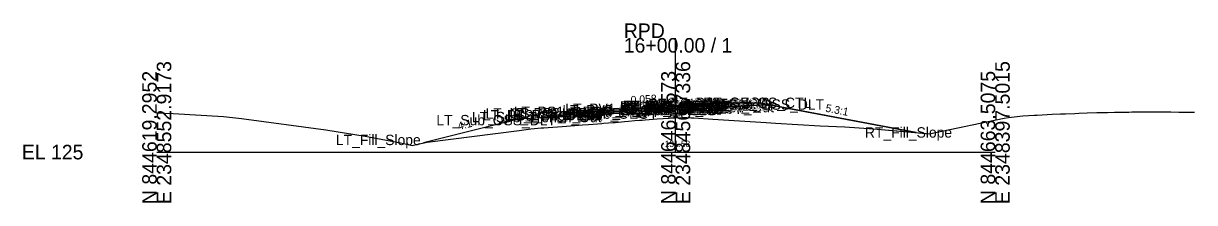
# Model space of a CAD drawing. Extents: x -26 to 2348536, y -510 to 844755.
# Drawn here: x -25.7 to 200, y 990.3 to 1024.7 of the extents above; entities that cross this region are included whole.
import ezdxf

# ---------------------------------------------------------------- set-up
doc = ezdxf.new("R2010")
doc.units = 0
for name, color, linetype in [('Default', 7, 'Continuous'), ('Exist Cross Section Cell', 7, 'Continuous'), ('Exist XS Center Line Elevation Label', 7, 'Continuous'), ('Exist XS Ground Line', 7, 'Continuous'), ('Prop CMT Pvmt Course 1', 7, 'Continuous'), ('Prop CMT Pvmt Course 2', 7, 'Continuous'), ('Prop CMT Pvmt Course 3', 7, 'Continuous'), ('Prop CMT Pvmt Surface', 7, 'Continuous'), ('Prop CMT Pvmt Surface Shoulder', 7, 'Continuous'), ('Prop CMT Shld Paved Course 1', 7, 'Continuous'), ('Prop CMT Shld Paved Course 2', 7, 'Continuous'), ('Prop CMT Shld Paved Course 3', 7, 'Continuous'), ('Prop CMT Slope Grass', 7, 'Continuous'), ('Prop CMT Subgrade Earthwork', 7, 'Continuous'), ('Prop XS Earthwork Shape', 7, 'Continuous'), ('Prop XS SE Text', 7, 'Continuous'), ('Prop XS Side Slope Text', 7, 'Continuous'), ('Scratch_Level_0', 7, 'Continuous')]:
    doc.layers.add(name, color=color, linetype=linetype)

msp = doc.modelspace()

# ---------------------------------------------------------------- linework, layer by layer
at = {"layer": 'Exist Cross Section Cell'}
for p, q in [((100, 1000), (100, 1021.92)), ((0, 1000), (100, 1000)), ((100, 1000), (161.58, 1000))]:
    msp.add_line(p, q, dxfattribs=at)
at = {"layer": 'Exist XS Ground Line'}
msp.add_lwpolyline([(0, 1007.56), (3.17, 1007.41), (12.86, 1006.84), (16.33, 1006.47), (32.6, 1004.26), (40.16, 1003.07), (46.36, 1001.88), (48.21, 1001.49), (49.24, 1001.27), (50.29, 1001.51), (52.09, 1001.91), (69.82, 1004.17), (72.12, 1004.46), (72.79, 1004.52), (74.06, 1004.63), (74.62, 1004.67), (75.4, 1004.7), (78.12, 1004.91), (80.54, 1005.11), (82.06, 1005.22), (83.2, 1005.31), (84.12, 1005.38), (85.78, 1005.5), (86.09, 1005.53), (87.03, 1005.62), (87.95, 1005.68), (88.34, 1005.7), (90.13, 1005.86), (90.94, 1005.93), (92.1, 1006.04), (93.04, 1006.13), (93.54, 1006.14), (94.15, 1006.19), (96.45, 1006.36), (98.75, 1006.54), (99.67, 1006.57), (100, 1006.58), (101.36, 1006.64), (102.15, 1006.62), (102.95, 1006.6), (103.53, 1006.58), (107.14, 1006.35), (117.43, 1005.67), (119.26, 1005.55), (127.83, 1005.04), (132.6, 1004.83), (138.12, 1004.47), (148.95, 1003.52), (149.75, 1003.68), (163.28, 1006.5), (164.11, 1006.62), (166.88, 1006.98), (167.97, 1007.02), (169.08, 1007.08), (169.66, 1007.11), (171.6, 1007.21), (172.54, 1007.26), (174.17, 1007.34), (175.13, 1007.38), (176.91, 1007.44), (177.69, 1007.5), (179.31, 1007.54), (181.17, 1007.58), (181.9, 1007.6), (183.24, 1007.63), (184.55, 1007.66), (187.34, 1007.7), (187.88, 1007.71), (189.94, 1007.72), (192.4, 1007.73), (194.21, 1007.72), (194.98, 1007.72), (195.42, 1007.72), (196.99, 1007.7), (197.8, 1007.69), (200, 1007.65)], dxfattribs=at)
at = {"layer": 'Prop CMT Pvmt Course 1'}
for p, q in [((100, 1009.01), (88, 1008.31)), ((100, 1009.01), (104, 1009.25)), ((100, 1008.76), (100, 1009.01)), ((100, 1008.76), (100, 1009.01)), ((104, 1009), (100, 1008.76)), ((100, 1008.76), (100, 1008.89)), ((100, 1008.89), (100, 1008.89)), ((100, 1008.89), (100, 1008.76)), ((100, 1008.76), (100, 1008.89)), ((100, 1008.89), (100, 1008.89)), ((100, 1008.89), (100, 1008.76)), ((104, 1009.25), (104, 1009)), ((88, 1008.06), (100, 1008.76)), ((88, 1008.31), (88, 1008.06)), ((100, 1008.76), (100, 1008.76)), ((100, 1008.76), (100, 1008.76))]:
    msp.add_line(p, q, dxfattribs=at)
at = {"layer": 'Prop CMT Pvmt Course 2'}
for p, q in [((100, 1008.76), (104, 1009)), ((104, 1009), (104, 1008.67)), ((100, 1008.76), (88, 1008.06)), ((88, 1007.73), (100, 1008.43)), ((88, 1008.06), (88, 1007.73)), ((100, 1008.43), (100, 1008.76)), ((100, 1008.43), (100, 1008.76)), ((104, 1008.67), (100, 1008.43))]:
    msp.add_line(p, q, dxfattribs=at)
at = {"layer": 'Prop CMT Pvmt Course 3'}
for p, q in [((100, 1008.43), (88, 1007.73)), ((88, 1007.4), (100, 1008.1)), ((88, 1007.73), (88, 1007.4)), ((100, 1008.43), (104, 1008.67)), ((100, 1008.1), (100, 1008.43)), ((100, 1008.1), (100, 1008.43)), ((104, 1008.33), (100, 1008.1)), ((104, 1008.67), (104, 1008.33))]:
    msp.add_line(p, q, dxfattribs=at)
at = {"layer": 'Prop CMT Pvmt Surface'}
for q in [(88, 1008.31), (104, 1009.25)]:
    msp.add_line((100, 1009.01), q, dxfattribs=at)
at = {"layer": 'Prop CMT Pvmt Surface Shoulder'}
for p, q in [((104, 1009.25), (108, 1009.48)), ((88, 1008.31), (78, 1007.73))]:
    msp.add_line(p, q, dxfattribs=at)
at = {"layer": 'Prop CMT Shld Paved Course 1'}
for p, q in [((104, 1009.25), (108, 1009.48)), ((108.24, 1009.25), (104, 1009)), ((104, 1009), (104, 1009.25)), ((108, 1009.48), (108.24, 1009.25)), ((77.73, 1007.46), (88, 1008.06)), ((78, 1007.73), (77.73, 1007.46)), ((88, 1008.31), (78, 1007.73)), ((88, 1008.06), (88, 1008.31))]:
    msp.add_line(p, q, dxfattribs=at)
at = {"layer": 'Prop CMT Shld Paved Course 2'}
for p, q in [((104, 1009), (108.24, 1009.25)), ((104, 1008.67), (104, 1009)), ((108.55, 1008.93), (104, 1008.67)), ((108.24, 1009.25), (108.55, 1008.93)), ((77.38, 1007.11), (88, 1007.73)), ((77.73, 1007.46), (77.38, 1007.11)), ((88, 1008.06), (77.73, 1007.46)), ((88, 1007.73), (88, 1008.06))]:
    msp.add_line(p, q, dxfattribs=at)
at = {"layer": 'Prop CMT Shld Paved Course 3'}
for p, q in [((104, 1008.67), (108.55, 1008.93)), ((108.55, 1008.93), (109.05, 1008.96)), ((109.05, 1008.96), (109.37, 1008.65)), ((76.53, 1006.73), (88, 1007.4)), ((76.88, 1007.08), (76.53, 1006.73)), ((77.38, 1007.11), (76.88, 1007.08)), ((88, 1007.73), (77.38, 1007.11)), ((88, 1007.4), (88, 1007.73)), ((104, 1008.33), (104, 1008.67)), ((109.37, 1008.65), (104, 1008.33))]:
    msp.add_line(p, q, dxfattribs=at)
at = {"layer": 'Prop CMT Slope Grass'}
for p, q in [((108, 1009.48), (116, 1009.47)), ((116, 1009.47), (146.33, 1003.75)), ((74, 1007.41), (51.39, 1001.76)), ((78, 1007.73), (74, 1007.41))]:
    msp.add_line(p, q, dxfattribs=at)
at = {"layer": 'Prop CMT Subgrade Earthwork'}
for p, q in [((109.37, 1008.65), (117.76, 1009.14)), ((76.53, 1006.73), (69.66, 1006.32)), ((88, 1007.4), (76.53, 1006.73)), ((100, 1008.1), (88, 1007.4)), ((100, 1008.1), (104, 1008.33)), ((104, 1008.33), (109.37, 1008.65))]:
    msp.add_line(p, q, dxfattribs=at)
at = {"layer": 'Prop XS Earthwork Shape'}
msp.add_lwpolyline([(69.66, 1006.32), (51.39, 1001.76), (52.09, 1001.91), (69.82, 1004.17), (72.12, 1004.46), (72.79, 1004.52), (74.06, 1004.63), (74.62, 1004.67), (75.4, 1004.7), (78.12, 1004.91), (80.54, 1005.11), (82.06, 1005.22), (83.2, 1005.31), (84.12, 1005.38), (85.78, 1005.5), (86.09, 1005.53), (87.03, 1005.62), (87.95, 1005.68), (88.34, 1005.7), (90.13, 1005.86), (90.94, 1005.93), (92.1, 1006.04), (93.04, 1006.13), (93.54, 1006.14), (94.15, 1006.19), (96.45, 1006.36), (98.75, 1006.54), (99.67, 1006.57), (100, 1006.58), (101.36, 1006.64), (102.15, 1006.62), (102.95, 1006.6), (103.53, 1006.58), (107.14, 1006.35), (117.43, 1005.67), (119.26, 1005.55), (127.83, 1005.04), (132.6, 1004.83), (138.12, 1004.47), (146.33, 1003.75), (117.76, 1009.14), (109.37, 1008.65), (104, 1008.33), (100, 1008.1), (88, 1007.4), (76.53, 1006.73)], close=True, dxfattribs=at)

# ---------------------------------------------------------------- texts
at = {"layer": 'Default'}
msp.add_text('-', height=0.0001, dxfattribs=at).set_placement((0, 1000))
at = {"layer": 'Exist Cross Section Cell'}
for s, p in [('RPD', (90, 1021.92)), ('16+00.00 / 1', (90, 1019.12)), ('EL 125', (-26, 998.6))]:
    msp.add_text(s, height=2.8, dxfattribs=at).set_placement(p)
for s, p in [('E 2348552.9173', (2.8, 990)), ('E 2348456.7336', (102.8, 990)), ('E 2348397.5015', (164.38, 990)), ('N 844619.2952', (0, 990)), ('N 844646.6573', (100, 990)), ('N 844663.5075', (161.58, 990))]:
    msp.add_text(s, height=2.8, rotation=90, dxfattribs=at).set_placement(p)
at = {"layer": 'Exist XS Center Line Elevation Label'}
msp.add_text('131.58', height=1.2, dxfattribs=at).set_placement((97.89, 1000.98))
at = {"layer": 'Prop XS SE Text'}
msp.add_text('0.058', height=1.5, rotation=3.3456, dxfattribs=at).set_placement((91.38, 1009.27))
at = {"layer": 'Prop XS Side Slope Text'}
for s, rotation, p in [('5.3:1', 349.2411, (128.79, 1007.78)), ('4:1', 14.0362, (58.2, 1004.22))]:
    msp.add_text(s, height=1.5, rotation=rotation, dxfattribs=at).set_placement(p)
at = {"layer": 'Scratch_Level_0'}
for s, p in [('LT_PV2_OEOT', (78.17, 1007.06)), ('LT_PV1_OEOT', (78.74, 1007.31)), ('RT_Sub_OEEOP', (89.17, 1007.1)), ('LT_Sub_OEEOP', (89.21, 1007.1)), ('RT_PV2_OEEOP', (89.26, 1007.76)), ('RT_PV3_OEEOP', (89.26, 1007.43)), ('LT_PV2_OEEOP', (89.31, 1007.76)), ('LT_PV3_OEEOP', (89.31, 1007.43)), ('RT_PV1_OEEOP', (89.83, 1007.89)), ('LT_PV1_OEEOP', (89.87, 1007.89)), ('RT_PV2_IEEOP', (89.91, 1007.76)), ('LT_PV2_IEEOP', (89.95, 1007.76)), ('RT_PV1_IEEOP', (90.47, 1007.89)), ('LT_PV1_IEEOP', (90.52, 1007.89)), ('RT_Sub_Trench_Out', (93.52, 1007.65)), ('PV2_PGL', (93.91, 1007.76)), ('RT_Sub_OEOT', (94.03, 1007.33)), ('RT_PV2_OEOT', (94.13, 1008)), ('RT_PV3_OEOT', (94.13, 1007.67)), ('PV1_PGL', (94.47, 1008.01)), ('RT_PV1_OEOT', (94.69, 1008.25)), ('RT_PS3_Shelf_Out', (94.99, 1007.96)), ('RT_PS2_OEOP', (98.43, 1008.25)), ('RT_PS3_OEOP', (98.74, 1007.93)), ('RT_PS1_OEOP', (98.76, 1008.48)), ('RT_Sub_OSS_DLT', (105.11, 1008.14)), ('RT_GS_OS_CTL', (105.32, 1008.47)), ('LT_Sub_OSS_DLT', (53.89, 1005.14)), ('LT_Sub_Trench_Out', (60.73, 1005.73)), ('LT_PS3_Shelf_Out', (62.86, 1006.08)), ('LT_GS_OS_CTL', (63.37, 1006.41)), ('LT_PS3_OEOP', (67.62, 1006.11)), ('LT_PS2_OEOP', (67.97, 1006.46)), ('LT_PS1_OEOP', (68.8, 1006.73)), ('LT_Sub_OEOT', (78.08, 1006.4)), ('LT_PV3_OEOT', (78.17, 1006.73)), ('RT_Fill_Slope', (136.47, 1002.78)), ('LT_Fill_Slope', (34.52, 1001.34))]:
    msp.add_text(s, height=2, dxfattribs=at).set_placement(p)

doc.saveas('drawing.dxf')
